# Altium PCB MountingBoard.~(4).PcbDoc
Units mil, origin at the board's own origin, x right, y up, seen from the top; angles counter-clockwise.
Board outline 3780 x 10000 mil, 4 copper layers (Top Layer, Internal Plane 1, Internal Plane 2, Bottom Layer); 6 components, 5 nets, 12 pads, 8 vias.
Unrouted connection lines stored in the file: 6.
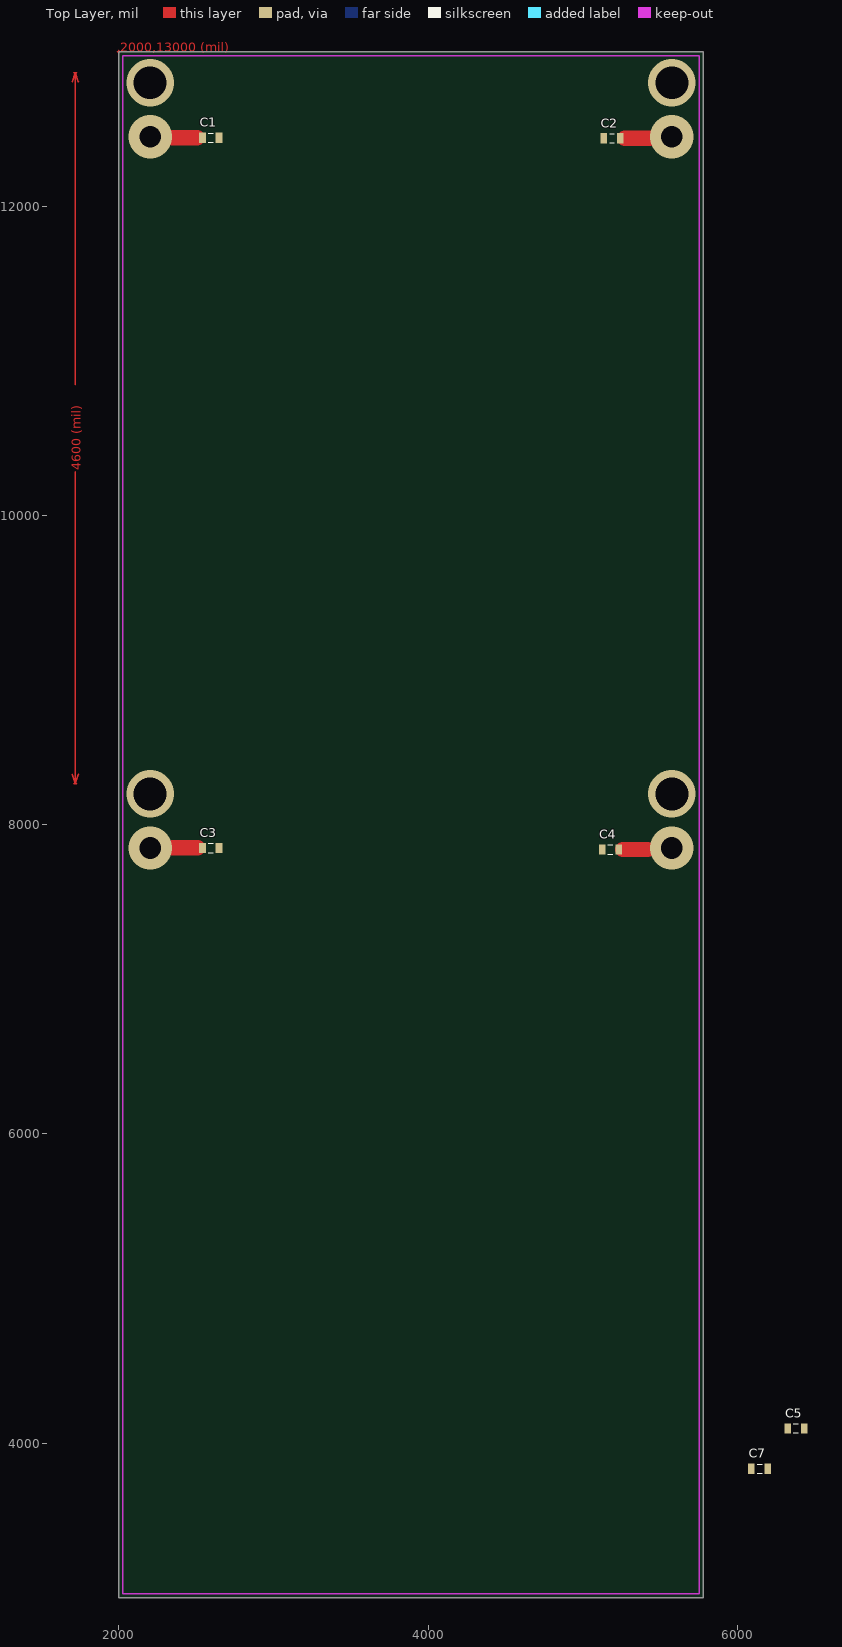
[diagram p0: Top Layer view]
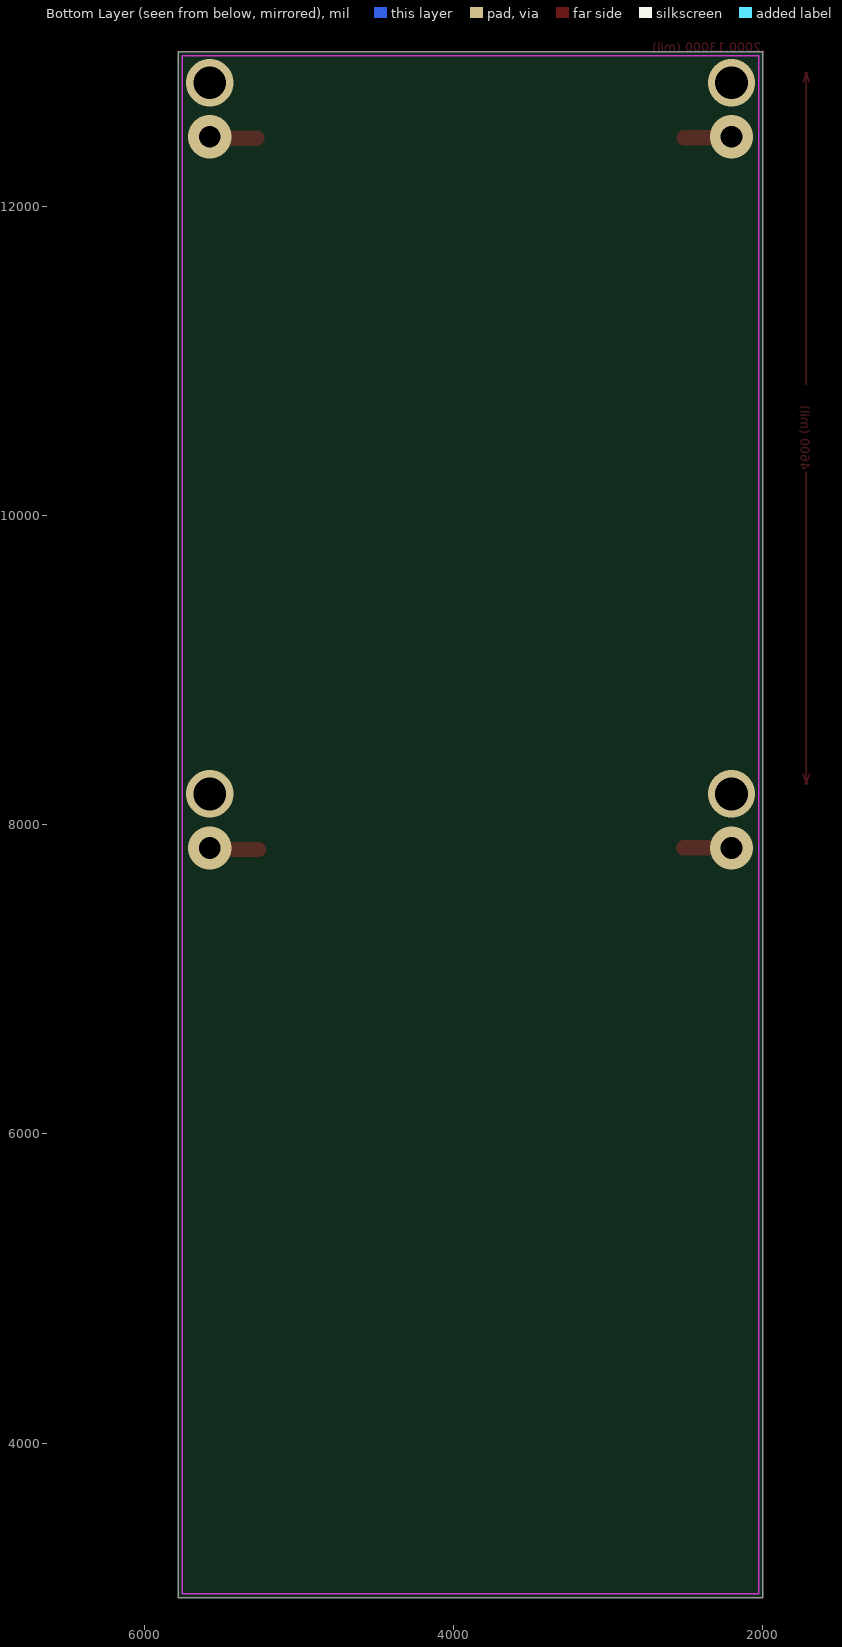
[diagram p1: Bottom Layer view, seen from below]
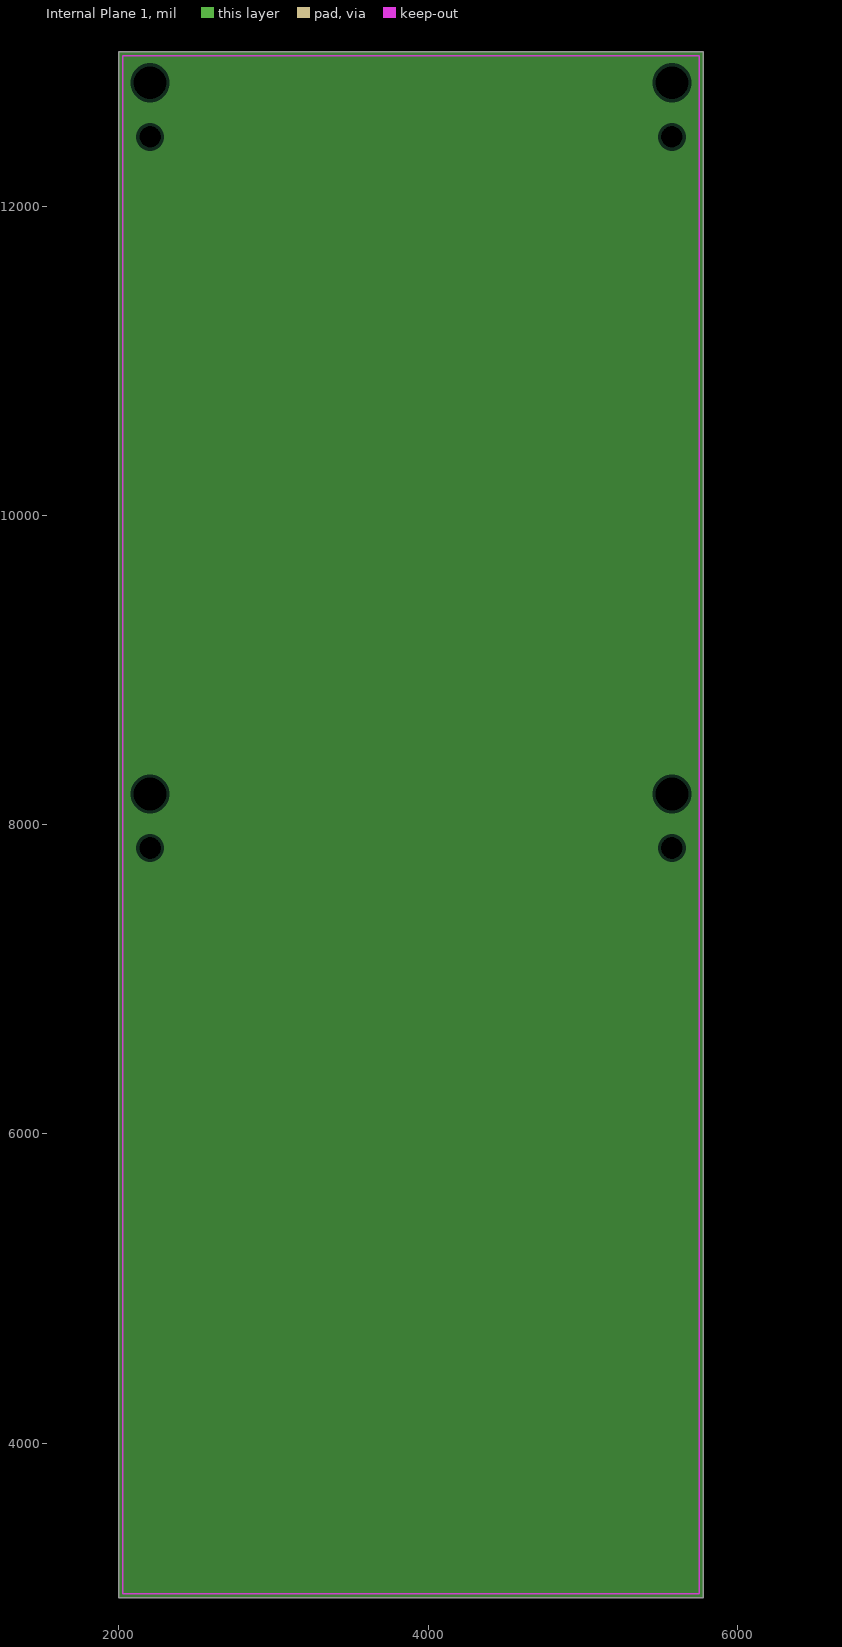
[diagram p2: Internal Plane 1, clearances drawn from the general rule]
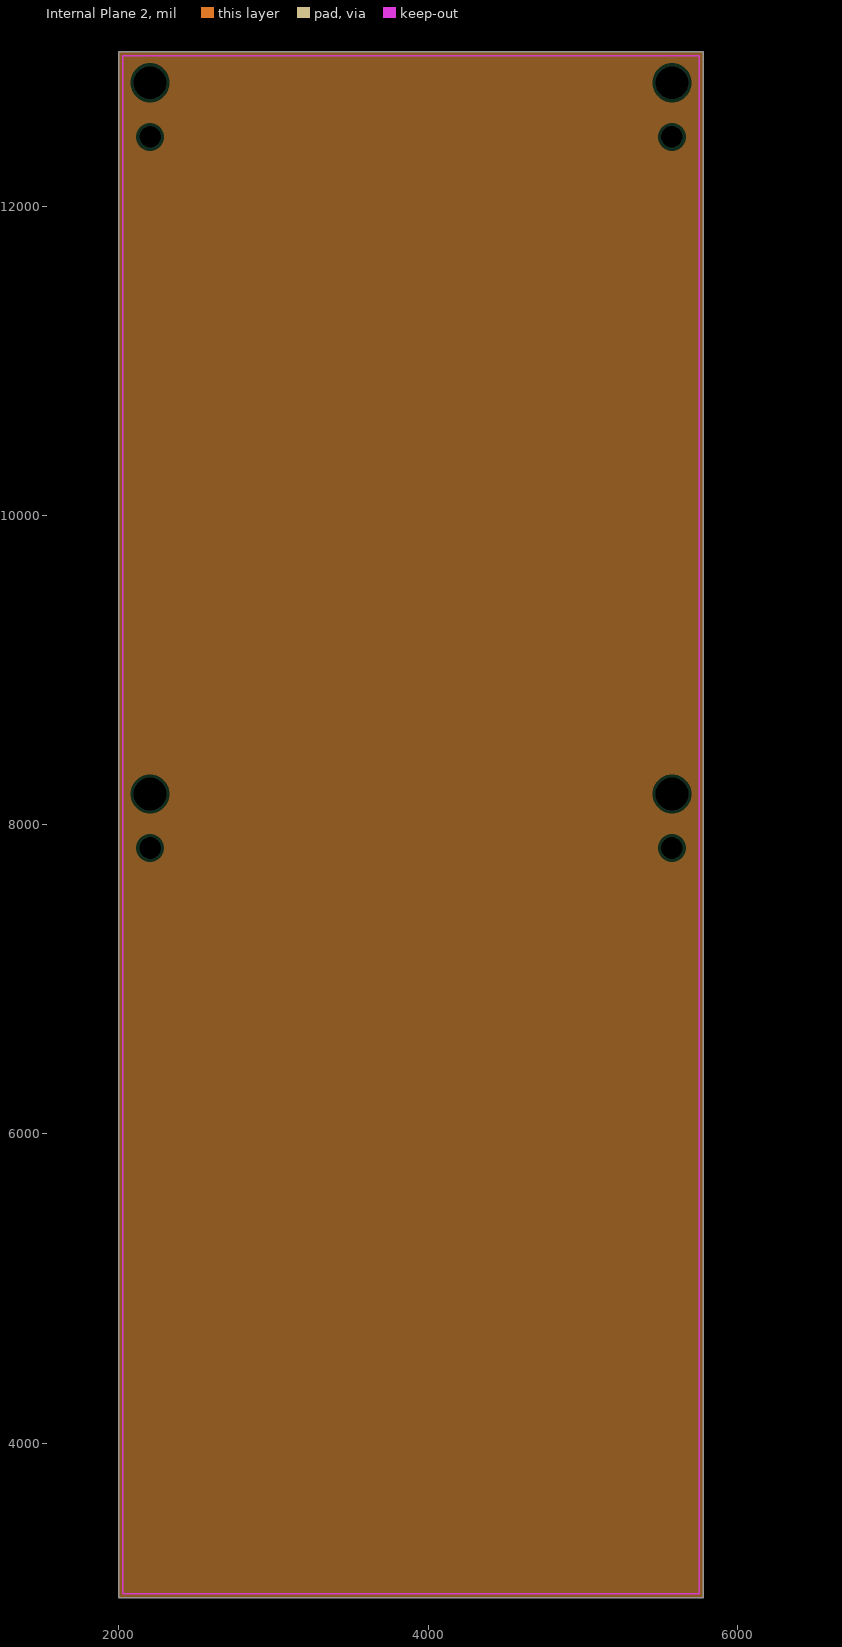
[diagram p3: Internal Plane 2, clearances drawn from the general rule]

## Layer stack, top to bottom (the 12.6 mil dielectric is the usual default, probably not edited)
Top Layer: signal copper 1.4
Dielectric: dielectric 12.6, FR-4, Dk 4.8
Internal Plane 1: plane copper 1.4
Dielectric: dielectric 12.6, FR-4, Dk 4.8
Internal Plane 2: plane copper 1.4
Dielectric: dielectric 12.6, FR-4, Dk 4.8
Bottom Layer: signal copper 1.4

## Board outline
2000,3000 5780,3000 5780,13000 2000,13000

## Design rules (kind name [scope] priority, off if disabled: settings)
Clearance [All] p1: gap=8
PlaneClearance [All] p1: clearance=20
PlaneConnect [All] p1: planeconnectstyle=Direct reliefexpansion=20 reliefentries=4 reliefconductorwidth=10 reliefairgap=10
PolygonConnect [All] p1: connectstyle=Direct reliefconductorwidth=10 reliefentries=4 polygonreliefangle="90 Angle"
RoomDefinition MountingBoard [InComponentClass('MountingBoard')] p1: confinementstyle=ConfineIn formatcopy=TRUE lockcomponents=FALSE outline 5825,3060 6215,3060 6215,3250 5825,3250
RoutingVias [All] p1: holewidth=28 width=50 viastyle="Through Hole" minholewidth=28 minwidth=50 maxholewidth=28 maxwidth=50
SilkscreenOverComponentPads [All] p1: minsilkscreentomaskgap=10
SolderMaskExpansion [All] p1: expansion=4
Width [All] p1: maxlimit=10 minlimit=10 preferedwidth=10
25 further rules are at their usual default settings.

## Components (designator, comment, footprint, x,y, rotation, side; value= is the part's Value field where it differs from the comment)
C1 "Cap Semi" CAPC3216L 2595,12445 r0 top
C2 "Cap Semi" CAPC3216L 5190,12440 r180 top
C3 "Cap Semi" CAPC3216L 2595,7850 r0 top
C4 "Cap Semi" CAPC3216L 5180,7840 r180 top
C5 "Cap Semi" CAPC3216L 6380,4095 r0 top
C7 "Cap Semi" CAPC3216L 6145,3835 r0 top

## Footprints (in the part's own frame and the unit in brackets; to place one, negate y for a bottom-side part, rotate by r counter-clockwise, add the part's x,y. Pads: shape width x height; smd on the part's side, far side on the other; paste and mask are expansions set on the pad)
CAPC3216L [mm] "Chip Capacitor, Body 3.2x1.6mm, IPC High Density"
  rect 1.1x1.7 smd: 1(-1.35,0) 2(1.35,0)
  silkscreen extent -0.4,-0.75 0.4,0.75, body extent -1.7,-0.9 1.7,0.9, height 1.3

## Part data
C1 C2 C3 C4 C5 C7: "Capacitor (Semiconductor SIM Model)"

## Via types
v1: diameter 280, hole 140, Top Layer to Bottom Layer, 4 vias
v2: diameter 306, hole 213, Top Layer to Bottom Layer, 4 vias

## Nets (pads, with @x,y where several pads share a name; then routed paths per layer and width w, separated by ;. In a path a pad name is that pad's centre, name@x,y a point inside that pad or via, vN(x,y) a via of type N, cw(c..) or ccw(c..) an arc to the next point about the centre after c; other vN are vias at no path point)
BUS+: 
BUS-: 
CHASSIS: C1.1 C2.1 C3.1 C4.1 C5.1 C7.2 | length 647.4
  Top Layer w100: 2345,12445 2506.85,12445 ; 2350,7850 2511.85,7850 ; 5260,7840 5421.85,7840 ; 5273.15,12440 5435,12440
  other v1: 2202.5,7850 5577.5,7850 2202.5,12450 5577.5,12450
"EDGETECH GROUND": C1.2 C2.2 C3.2 C4.2 C7.1
  other v2: 2202.5,8200 5577.5,8200 2202.5,12800 5577.5,12800
"FILTER BUS+": C5.2
copper on no net: | length 4371.2
  Top Layer w10: 1699.01,8325.91 1719.01,8265.91 ; 1699.01,12805.91 1719.01,12865.91 ; 1709.01,8265.91 1729.01,8265.91 ; 1709.01,12865.91 1729.01,12865.91 ; 1719.01,10285 1719.01,8265.91 ; 1719.01,10846.83 1719.01,12865.91 ; 1739.01,8325.91 1719.01,8265.91 ; 1739.01,12805.91 1719.01,12865.91 ; 1990,13000 2010,13000 ; 2000,12990 2000,13010

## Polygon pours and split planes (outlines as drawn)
no net on Internal Plane 1 (split plane): 5780,3000 2000,3000 2000,13000 5780,13000
no net on Internal Plane 2 (split plane): 5780,3000 2000,3000 2000,13000 5780,13000

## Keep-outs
Keep-Out Layer:
  lines w10: 2025,3025 2025,12975 5755,12975 5755,3025 2025,3025

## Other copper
Top Layer:
  text "2000,13000 (mil)" at 2010,13000 h60
  text "4600 (mil)" at 1755,10295 h60 r90

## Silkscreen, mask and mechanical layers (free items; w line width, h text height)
Drill Drawing:
  text ".LEGEND" at 5980,3200 h60
  text "Drill Drawing." at 5980,3100 h60

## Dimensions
2202.5,12800 to 5577.5,12800 on Top Layer
2025,3025 to 2025,12975 on Mechanical 1
2025,3025 to 5755,3025 on Mechanical 1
